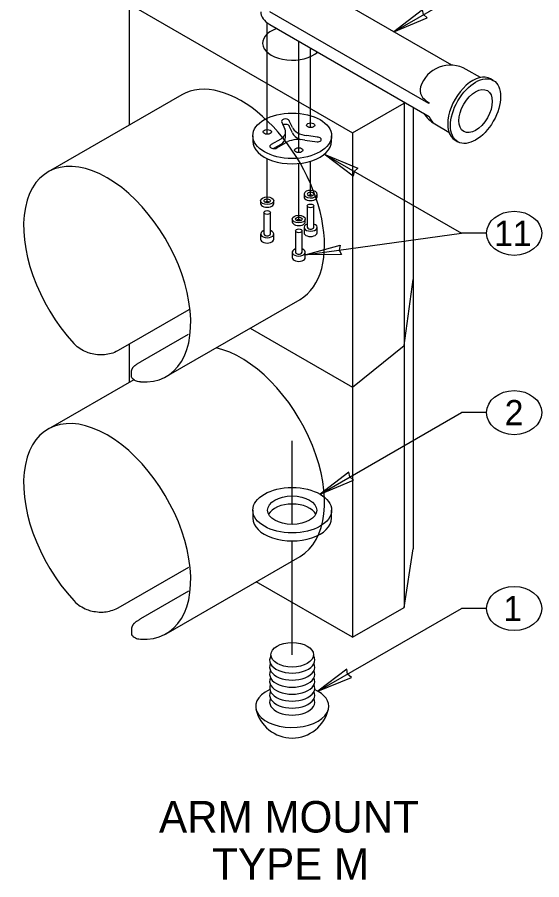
# Model space of a CAD drawing. Extents: x 99862 to 104211, y 98939 to 105076.
# Drawn here: x 101343 to 101676, y 101087 to 101635 of the extents above; entities that cross this region are included whole.
import ezdxf

# ---------------------------------------------------------------- set-up
doc = ezdxf.new("R2010")
doc.units = 0
for name, color, linetype in [('Level 1', 7, 'Continuous'), ('Level 11', 7, 'Continuous'), ('Level 12', 7, 'Continuous'), ('Level 15', 7, 'Continuous'), ('Level 19', 7, 'Continuous'), ('Level 2', 7, 'Continuous'), ('Level 20', 7, 'Continuous'), ('Level 26', 7, 'Continuous')]:
    doc.layers.add(name, color=color, linetype=linetype)

msp = doc.modelspace()

# ---------------------------------------------------------------- linework, layer by layer
at = {"layer": 'Level 1'}
msp.add_arc((101517.77, 101200.43), 23.6, 192.7466, 347.2534, dxfattribs=at)
msp.add_ellipse((101517.77, 101229.67), major_axis=(-13.49, 0), ratio=0.57735, dxfattribs=at)
for centre, major_axis, start_param, end_param in [((101517.77, 101226.33), (14.31, 0), 2.795302, 6.629476), ((101517.77, 101221.88), (14.31, 0), 2.86885, 6.555928), ((101517.77, 101217.34), (14.31, 0), 2.86338, 6.561398), ((101517.77, 101212.89), (14.31, 0), 2.86885, 6.555928), ((101517.77, 101208.53), (14.31, 0), 2.874311, 6.550467), ((101517.77, 101196.96), (23.21, 0), 2.229419, 6.153315), ((101517.77, 101204.08), (14.31, 0), 2.86885, 6.555928), ((101517.77, 101196.96), (23.21, 0), 6.153315, 7.195359), ((101517.77, 101199.63), (14.31, 0), 2.86885, 6.555928)]:
    msp.add_ellipse(centre, major_axis=major_axis, ratio=0.57735, start_param=start_param, end_param=end_param, dxfattribs=at)
at = {"layer": 'Level 11'}
for p, q in [((101510.92, 101568.41), (101513.14, 101563.45)), ((101517.9, 101564.6), (101516.13, 101568.41)), ((101513.54, 101558.32), (101513.54, 101561.72)), ((101517.9, 101561.2), (101516.13, 101565.01)), ((101492.77, 101559.27), (101492.77, 101555.87)), ((101510.46, 101557.17), (101504.33, 101553.64)), ((101525.7, 101556.54), (101533.61, 101555.31)), ((101533.61, 101558.32), (101527, 101559.34)), ((101542.77, 101555.87), (101542.77, 101559.27)), ((101510.46, 101553.77), (101505.81, 101551.08)), ((101508.02, 101551.51), (101514.94, 101555.51)), ((101497.76, 101517.97), (101497.76, 101516.27)), ((101506.1, 101516.27), (101506.1, 101517.97)), ((101525.27, 101522.18), (101525.27, 101520.48)), ((101533.61, 101520.48), (101533.61, 101522.18)), ((101527.36, 101514.72), (101527.36, 101501.11)), ((101531.52, 101501.11), (101531.52, 101514.72)), ((101499.85, 101510.52), (101499.85, 101496.91)), ((101504.01, 101496.91), (101504.01, 101510.52)), ((101517.75, 101506.36), (101517.75, 101504.66)), ((101526.08, 101504.66), (101526.08, 101506.36)), ((101525.27, 101501.11), (101525.27, 101497.71)), ((101533.61, 101497.71), (101533.61, 101501.11)), ((101497.76, 101496.91), (101497.76, 101493.51)), ((101506.1, 101493.51), (101506.1, 101496.91)), ((101519.83, 101498.91), (101519.83, 101485.3)), ((101524, 101485.3), (101524, 101498.91)), ((101517.75, 101485.3), (101517.75, 101481.9)), ((101526.08, 101481.9), (101526.08, 101485.3))]:
    msp.add_line(p, q, dxfattribs=at)
for centre, major_axis in [((101517.77, 101559.27), (-25, 0)), ((101529.44, 101565.92), (-2.6, 0)), ((101501.93, 101561.72), (-2.6, 0)), ((101521.92, 101550.11), (-2.6, 0)), ((101501.93, 101517.97), (-4.17, 0)), ((101501.93, 101517.97), (-2.08, 0)), ((101501.93, 101510.52), (-2.08, 0)), ((101529.44, 101514.72), (-2.08, 0)), ((101521.92, 101506.36), (-4.17, 0)), ((101521.92, 101506.36), (-2.08, 0)), ((101521.92, 101498.91), (-2.08, 0))]:
    msp.add_ellipse(centre, major_axis=major_axis, ratio=0.57735, dxfattribs=at)
for centre, major_axis, start_param, end_param in [((101513.53, 101568.41), (-2.6, 0), 3.141593, 6.283185), ((101513.53, 101565.01), (-2.6, 0), 3.141593, 5.379094), ((101501.93, 101561.72), (-11.61, 0), 2.396309, 3.403392), ((101529.37, 101565.96), (-11.71, 0), 0.203445, 1.367352), ((101529.37, 101562.56), (-11.71, 0), 0.203445, 1.005854), ((101517.77, 101555.87), (-25, 0), 6.283185, 9.424778), ((101501.93, 101558.32), (-11.61, 0), 2.396309, 3.141593), ((101522.02, 101550.12), (-11.71, 0), 4.392235, 5.361438), ((101533.61, 101556.82), (-2.6, 0), 1.570796, 4.712389), ((101506.18, 101552.57), (-2.6, 0), 5.497787, 8.63938), ((101529.44, 101522.18), (-4.17, 0), 0.321913, 6.60445), ((101529.44, 101522.18), (-2.08, 0), 0.014662, 6.283185), ((101501.93, 101516.27), (-2.08, 0), 3.926991, 5.497787), ((101529.44, 101520.48), (-4.17, 0), 0, 3.141593), ((101529.44, 101520.48), (-2.08, 0), 3.926991, 5.497787), ((101501.93, 101516.27), (-4.17, 0), 0, 3.141593), ((101521.92, 101504.66), (-4.17, 0), 6.283185, 9.424778), ((101521.92, 101504.66), (-2.08, 0), 3.926991, 5.497787), ((101529.44, 101501.11), (-4.17, 0), 5.235988, 10.471976), ((101529.44, 101501.11), (-2.08, 0), 6.283185, 9.424778), ((101501.93, 101496.91), (-4.17, 0), 5.235988, 10.471976), ((101501.93, 101496.91), (-2.08, 0), 0, 3.141593), ((101529.44, 101497.71), (-4.17, 0), 6.283185, 9.424778), ((101501.93, 101493.51), (-4.17, 0), 6.283185, 9.424778), ((101521.92, 101485.3), (-4.17, 0), 5.235988, 10.471976), ((101521.92, 101485.3), (-2.08, 0), 6.283185, 9.424778), ((101521.92, 101481.9), (-4.17, 0), 6.283185, 9.424778)]:
    msp.add_ellipse(centre, major_axis=major_axis, ratio=0.57735, start_param=start_param, end_param=end_param, dxfattribs=at)
at = {"layer": 'Level 12'}
for p, q in [((101618.94, 101604.1), (101532.64, 101653.92)), ((101604.42, 101579.82), (101503.63, 101638.01)), ((101503.63, 101629.84), (101604.68, 101571.5)), ((101637.19, 101596.24), (101628.2, 101601.43)), ((101645.36, 101594.41), (101643.59, 101595.43)), ((101608.2, 101566.79), (101617.19, 101561.6)), ((101621.09, 101556.46), (101622.86, 101555.44))]:
    msp.add_line(p, q, dxfattribs=at)
for start, end in [(60, 162.1705), (212.1144, 240)]:
    msp.add_arc((101618.2, 101584.11), 20, start, end, dxfattribs=at)
for centre, major_axis, start_param, end_param in [((101517.77, 101638.01), (20, 0), 3.141593, 3.926991), ((101632.34, 101575.94), (11.25, 19.49), 0, 3.141593), ((101618.2, 101588.19), (-19.36, 0), 6.099581, 7.068583), ((101618.2, 101584.11), (10, 17.32), 2.103514, 2.129786), ((101618.2, 101584.11), (10, 17.32), 2.654898, 3.141593)]:
    msp.add_ellipse(centre, major_axis=major_axis, ratio=0.57735, start_param=start_param, end_param=end_param, dxfattribs=at)
for major_axis in [(11.25, 19.49), (-7.5, -12.99)]:
    msp.add_ellipse((101634.11, 101574.92), major_axis=major_axis, ratio=0.57735, dxfattribs=at)
at = {"layer": 'Level 15'}
for p, q in [((101582.24, 101625.28), (101627.26, 101651.27)), ((101501.93, 101560.21), (101501.93, 101630.96)), ((101521.92, 101548.6), (101521.92, 101619.29)), ((101529.37, 101564.42), (101529.37, 101614.98)), ((101501.93, 101516.77), (101501.93, 101544.7)), ((101538.15, 101547.5), (101625.08, 101497.31)), ((101521.92, 101505.16), (101521.92, 101541.63)), ((101529.37, 101520.98), (101529.37, 101543.08)), ((101526.08, 101483.6), (101625.08, 101497.31)), ((101641.08, 101497.31), (101625.08, 101497.31)), ((101535.45, 101331.7), (101625.08, 101383.45)), ((101641.08, 101383.45), (101625.08, 101383.45)), ((101517.77, 101312.47), (101517.77, 101365.59)), ((101517.77, 101229.67), (101517.77, 101301.96)), ((101534.06, 101206.51), (101625.08, 101259.06)), ((101641.08, 101259.06), (101625.08, 101259.06))]:
    msp.add_line(p, q, dxfattribs=at)
for points in [[(101582.24, 101625.28), (101603.5, 101634.11), (101601.1, 101636.17), (101600.52, 101639.28)], [(101538.15, 101547.5), (101559.41, 101538.67), (101557, 101536.62), (101556.43, 101533.5)], [(101526.08, 101483.6), (101548.29, 101489.69), (101547.65, 101486.58), (101549.11, 101483.77)], [(101535.45, 101331.7), (101556.71, 101340.53), (101554.31, 101342.59), (101553.73, 101345.7)], [(101534.06, 101206.51), (101555.32, 101215.34), (101552.91, 101217.4), (101552.33, 101220.51)]]:
    msp.add_lwpolyline(points, close=True, dxfattribs=at)
at = {"layer": 'Level 19'}
for p, q in [((101588.71, 101426.06), (101594.59, 101468.06)), ((101555.95, 101399.57), (101588.71, 101426.06))]:
    msp.add_line(p, q, dxfattribs=at)
at = {"layer": 'Level 2'}
for p, q in [((101492.77, 101321.49), (101492.77, 101316.39)), ((101542.77, 101316.39), (101542.77, 101321.49))]:
    msp.add_line(p, q, dxfattribs=at)
for major_axis in [(25, 0), (15.62, 0)]:
    msp.add_ellipse((101517.77, 101321.49), major_axis=major_axis, ratio=0.57735, dxfattribs=at)
for major_axis, start_param, end_param in [((-15.62, 0), 3.428349, 5.996429), ((-25, 0), 0, 3.141593)]:
    msp.add_ellipse((101517.77, 101316.39), major_axis=major_axis, ratio=0.57735, start_param=start_param, end_param=end_param, dxfattribs=at)
at = {"layer": 'Level 20'}
for centre in [(101658.58, 101497.31), (101658.58, 101383.45), (101658.58, 101259.06)]:
    msp.add_ellipse(centre, major_axis=(-17.5, 0), ratio=0.8, dxfattribs=at)
at = {"layer": 'Level 26'}
for p, q in [((101414.53, 101642.78), (101555.95, 101561.13)), ((101414.53, 101566.08), (101414.53, 101642.78)), ((101447.74, 101585.26), (101362.88, 101536.27)), ((101555.95, 101561.13), (101588.71, 101580.05)), ((101588.71, 101580.05), (101588.81, 101580.66)), ((101588.71, 101580.05), (101588.71, 101259.71)), ((101594.59, 101577.33), (101594.59, 101297.01)), ((101555.95, 101561.13), (101555.95, 101240.79)), ((101437.88, 101406.36), (101522.74, 101455.35)), ((101452.15, 101448.68), (101407.46, 101422.87)), ((101491.04, 101437.05), (101555.95, 101399.57)), ((101421.6, 101415.74), (101452.05, 101433.32)), ((101414.53, 101402.78), (101414.53, 101426.96)), ((101415.74, 101407.38), (101415.74, 101408.43)), ((101417.26, 101404.36), (101362.88, 101372.97)), ((101588.71, 101259.71), (101594.59, 101297.01)), ((101437.88, 101243.06), (101522.74, 101292.05)), ((101407.46, 101259.57), (101452.15, 101285.38)), ((101555.95, 101240.79), (101494.95, 101276.01)), ((101452.05, 101270.02), (101421.6, 101252.44)), ((101555.95, 101240.79), (101588.71, 101259.71)), ((101415.74, 101245.13), (101415.74, 101244.08))]:
    msp.add_line(p, q, dxfattribs=at)
for centre, major_axis, start_param, end_param in [((101517.77, 101618.04), (18.75, 0), 2.116379, 5.737603), ((101485.24, 101520.31), (37.5, -64.95), 0, 3.141593), ((101400.38, 101471.32), (37.5, -64.95), 5.909304, 11.369456), ((101485.24, 101357.01), (37.5, -64.95), 0, 2.65862), ((101400.38, 101308.02), (37.5, -64.95), 5.909304, 11.369456)]:
    msp.add_ellipse(centre, major_axis=major_axis, ratio=0.57735, start_param=start_param, end_param=end_param, dxfattribs=at)
for points, degree in [([(101407.46, 101422.87), (101405.54, 101421.77), (101403.28, 101420.96), (101398.32, 101420.07), (101395.63, 101420.01), (101390.37, 101420.73), (101387.74, 101421.54), (101383.04, 101423.94), (101380.92, 101425.54), (101379.17, 101427.44)], 3), ([(101415.74, 101408.42), (101415.74, 101410.75), (101417.85, 101413.57), (101421.6, 101415.74)], 2), ([(101421.6, 101402.94), (101419.85, 101403.07), (101418.41, 101403.52), (101416.36, 101405.01), (101415.79, 101406.05), (101415.74, 101407.27), (101415.74, 101407.3), (101415.74, 101407.34)], 3), ([(101379.17, 101264.14), (101380.92, 101262.25), (101383.04, 101260.64), (101387.74, 101258.24), (101390.37, 101257.43), (101395.63, 101256.71), (101398.32, 101256.78), (101403.28, 101257.66), (101405.54, 101258.47), (101407.46, 101259.57)], 3), ([(101421.6, 101252.44), (101417.85, 101250.27), (101415.74, 101247.45), (101415.74, 101245.12)], 2), ([(101415.74, 101244.04), (101415.74, 101244.01), (101415.74, 101243.97), (101415.79, 101242.75), (101416.36, 101241.71), (101418.41, 101240.22), (101419.85, 101239.77), (101421.6, 101239.64)], 3)]:
    msp.add_open_spline(points, degree=degree, dxfattribs=at)

# ---------------------------------------------------------------- texts
at = {"layer": 'Level 20'}
for s, height, p in [('11', 16, (101645.85, 101489.31)), ('2', 16, (101652.59, 101375.45)), ('1', 16, (101651.71, 101251.07)), ('ARM MOUNT', 20, (101433.26, 101116.83)), ('TYPE M', 20, (101467.01, 101086.83))]:
    msp.add_text(s, height=height, dxfattribs=at).set_placement(p)

doc.saveas('drawing.dxf')
